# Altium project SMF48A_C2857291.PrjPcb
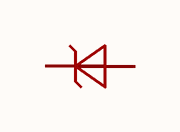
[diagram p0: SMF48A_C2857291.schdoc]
1 sheet, 1 parts. Net scope: global (net labels, ports and power ports of the same name join across sheets).

## Sheet SMF48A_C2857291.schdoc
size 127 x 101 mm

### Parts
D?  smf48a_c2857291  [SOD-123FL_L2.7-W1.8-LS3.7-RD]  (value not drawn)

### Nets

Not connected (* = marked no-connect by the designer): D? 1 2

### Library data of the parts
D? = smf48a_c2857291: 极性:单向;反向截止电压(Vrwm):48V;钳位电压:77.4V;峰值脉冲电流(Ipp):2.6A;峰值脉冲功率(Ppp):200W@10/1000us;击穿电压(VBR):53.3V;; Manufacturer: JSMSEMI(杰盛微); ManufacturerPart: SMF48A; AddInBom: yes; ModelId: 86f9151e155e4fe2af0c4f2e0a80302e; ModelName: SOD-123FL_L2.8-W1.8-H1.1-LS3.6; ModelTransform: 141.732,70.866,0,180,0,0,0,0,0; Polarity: 单向; Reverse Stand-Off Voltage (Vrwm): 48V; Clamping Voltage: 77.4V; Peak Pulse Current (Ipp): 2.6A; Voltage - Breakdown: 53.3V; Reverse Leakage Current (Ir): 1uA; Number of Channels: 单路; Type: TVS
